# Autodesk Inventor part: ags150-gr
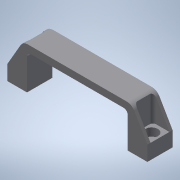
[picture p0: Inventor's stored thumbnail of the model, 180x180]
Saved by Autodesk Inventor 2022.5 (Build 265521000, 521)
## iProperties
Created: 2016-12
Part Number: ags150-gr
Material: 一般
Document SubType Name: Modeling
Designer: imaocorp
Density: 1 g/cm^3
Appearance: 既定
Author: imaocorp
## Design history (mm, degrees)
node "ags150-gr.x_t1"
node "ags150-gr"
node "Base1"
